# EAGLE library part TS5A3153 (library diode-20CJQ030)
Ti's TS5A3153 is a single-pole double-throw (SPDT) analog switch Description: The TS5A3153 is a single-pole double-throw (SPDT) analog switch that is designed to operate from 1.65 V to 5.5 V. The device offers a low ON-state resistance and an excellent on-resistance matching with the break-before-make feature, to prevent signal distortion during the transferring of a signal from one channel to another. The device has an excellent total harmonic distortion (THD) performance and consumes very low power. These features make this device suitable for portable audio applications. Features: Isolation in the Powered-Off Mode, V+ = 0 Specified Break-Before-Make Switching Low ON-State Resistance (1 ) Control Inputs Are 5.5-V Tolerant Low Charge Injection Excellent ON-State Resistance Matching Low Total Harmonic Distortion (THD) 1.65-V to 5.5-V Single-Supply Operation Latch-Up Performance Exceeds 100 mA Per JESD 78, Class II ESD Performance Tested Per JESD 22 - 2000-V Human-Body Model (A114-B, Class II) - 1000-V Charged-Device Model (C101) Applications: Cell Phones PDAs Portable Instrumentation Audio and Video Signal Routing Low-Voltage Data Acquisition System Communication Circuits Modems Hard Drives Computer Peripherals Wireless Terminals and Peripherals Please send any comments to: messi@users.sourceforge.net
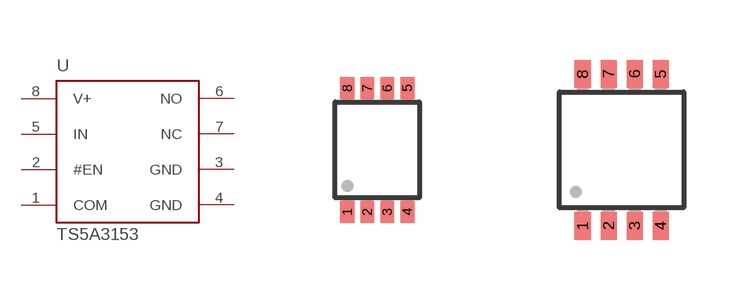
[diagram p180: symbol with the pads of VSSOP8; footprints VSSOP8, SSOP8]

Designator prefix U

## TS5A3153-DCU  [VSSOP8]
1  COM
2  #EN  in
3  GND  pwr
4  GND  pwr
5  IN  in
6  NO
7  NC
8  V+  pwr

## TS5A3153-DCT  [SSOP8]
Pads as for VSSOP8

## Footprint VSSOP8 (pad centres in mm)
smd 0.35 x 0.55: 1 -0.75,-1.55; 2 -0.25,-1.55; 3 0.25,-1.55; 4 0.75,-1.55; 5 0.75,1.55; 6 0.25,1.55; 7 -0.25,1.55; 8 -0.75,1.55

## Footprint SSOP8 (pad centres in mm)
smd 0.4 x 0.7: 1 -0.975,-1.9; 2 -0.325,-1.9; 3 0.325,-1.9; 4 0.975,-1.9; 5 0.975,1.9; 6 0.325,1.9; 7 -0.325,1.9; 8 -0.975,1.9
